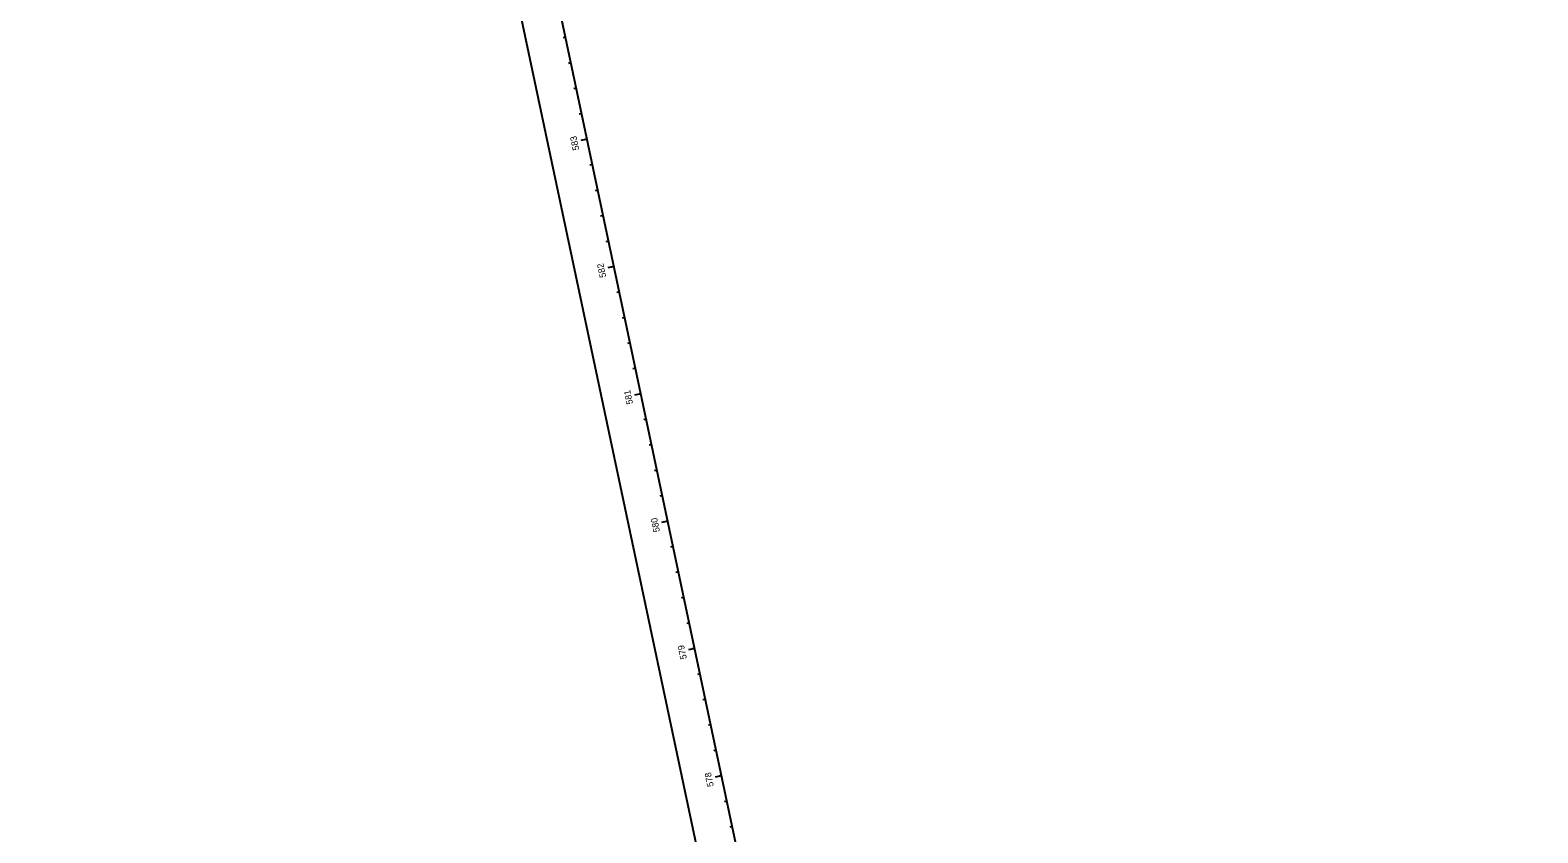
# Model space of a CAD drawing. Extents: x 2003883 to 2007688, y 399149 to 412300.
# Drawn here: x 2005065 to 2006224, y 405097 to 405714 of the extents above; entities that cross this region are included whole.
import ezdxf

# ---------------------------------------------------------------- set-up
doc = ezdxf.new("R2010")
doc.units = 0
for name, color, linetype in [('BaselineSurvey', 7, 'Continuous'), ('ConstLines', 7, 'Continuous'), ('Default', 7, 'Continuous'), ('TextAlgnStation100', 7, 'Continuous'), ('TextAlgnStation1000', 7, 'Continuous'), ('TextAlgnStation500', 7, 'Continuous'), ('TextAlgnTicks100', 7, 'Continuous'), ('TextAlgnTicks1000', 7, 'Continuous'), ('TextAlgnTicks500', 7, 'Continuous'), ('TextAlgnTicks5000', 7, 'Continuous')]:
    doc.layers.add(name, color=color, linetype=linetype)

msp = doc.modelspace()

# ---------------------------------------------------------------- linework, layer by layer
at = {"layer": 'BaselineSurvey'}
msp.add_line((2006223.9, 402174.4), (2005094.5, 407516), dxfattribs=at)
at = {"layer": 'ConstLines'}
msp.add_line((2006194.6, 402168.2), (2005065.1, 407509.8), dxfattribs=at)
at = {"layer": 'Default'}
msp.add_line((2006223.9, 402174.4), (2005094.5, 407516), dxfattribs=at)
at = {"layer": 'TextAlgnTicks100'}
for p, q in [((2005476.6, 405708.8), (2005474.7, 405708.4)), ((2005480.7, 405689.2), (2005478.8, 405688.8)), ((2005484.9, 405669.7), (2005482.9, 405669.2)), ((2005489, 405650.1), (2005487.1, 405649.7)), ((2005493.2, 405630.5), (2005488.3, 405629.5)), ((2005497.3, 405610.9), (2005495.3, 405610.5)), ((2005501.4, 405591.4), (2005499.5, 405591)), ((2005505.6, 405571.8), (2005503.6, 405571.4)), ((2005509.7, 405552.2), (2005507.7, 405551.8)), ((2005513.8, 405532.7), (2005509, 405531.6)), ((2005518, 405513.1), (2005516, 405512.7)), ((2005522.1, 405493.5), (2005520.2, 405493.1)), ((2005526.3, 405474), (2005524.3, 405473.6)), ((2005530.4, 405454.4), (2005528.4, 405454)), ((2005534.5, 405434.8), (2005529.6, 405433.8)), ((2005538.7, 405415.3), (2005536.7, 405414.9)), ((2005542.8, 405395.7), (2005540.8, 405395.3)), ((2005546.9, 405376.1), (2005545, 405375.7)), ((2005551.1, 405356.6), (2005549.1, 405356.2)), ((2005555.2, 405337), (2005550.3, 405336)), ((2005559.4, 405317.4), (2005557.4, 405317)), ((2005563.5, 405297.9), (2005561.5, 405297.5)), ((2005567.6, 405278.3), (2005565.7, 405277.9)), ((2005571.8, 405258.7), (2005569.8, 405258.3)), ((2005575.9, 405239.2), (2005571, 405238.1)), ((2005580, 405219.6), (2005578.1, 405219.2)), ((2005584.2, 405200), (2005582.2, 405199.6)), ((2005588.3, 405180.5), (2005586.4, 405180.1)), ((2005592.5, 405160.9), (2005590.5, 405160.5)), ((2005596.6, 405141.3), (2005591.7, 405140.3)), ((2005600.7, 405121.8), (2005598.8, 405121.4)), ((2005604.9, 405102.2), (2005602.9, 405101.8))]:
    msp.add_line(p, q, dxfattribs=at)
at = {"layer": 'TextAlgnTicks1000'}
for p, q in [((2005513.8, 405532.7), (2005511.9, 405532.3)), ((2005555.2, 405337), (2005550.3, 405336)), ((2005596.6, 405141.3), (2005594.6, 405140.9))]:
    msp.add_line(p, q, dxfattribs=at)
at = {"layer": 'TextAlgnTicks500'}
for p, q in [((2005493.2, 405630.5), (2005491.2, 405630.1)), ((2005513.8, 405532.7), (2005511.9, 405532.3)), ((2005534.5, 405434.8), (2005532.6, 405434.4)), ((2005555.2, 405337), (2005550.3, 405336)), ((2005575.9, 405239.2), (2005573.9, 405238.8)), ((2005596.6, 405141.3), (2005594.6, 405140.9))]:
    msp.add_line(p, q, dxfattribs=at)
at = {"layer": 'TextAlgnTicks5000'}
msp.add_line((2005555.2, 405337), (2005553.3, 405336.6), dxfattribs=at)

# ---------------------------------------------------------------- texts
at = {"layer": 'TextAlgnStation100'}
for s, p in [('583', (2005487.2, 405622.5)), ('582', (2005507.9, 405524.7)), ('581', (2005528.5, 405427.3)), ('580', (2005549.2, 405329.1)), ('579', (2005569.9, 405231.3)), ('578', (2005590.6, 405133.4))]:
    msp.add_text(s, height=4.98, rotation=101.9388, dxfattribs=at).set_placement(p)
at = {"layer": 'TextAlgnStation1000'}
msp.add_text('580', height=4.98, rotation=101.9388, dxfattribs=at).set_placement((2005549.2, 405329.1))
at = {"layer": 'TextAlgnStation500'}
msp.add_text('580', height=4.98, rotation=101.9388, dxfattribs=at).set_placement((2005549.2, 405329.1))

doc.saveas('drawing.dxf')
